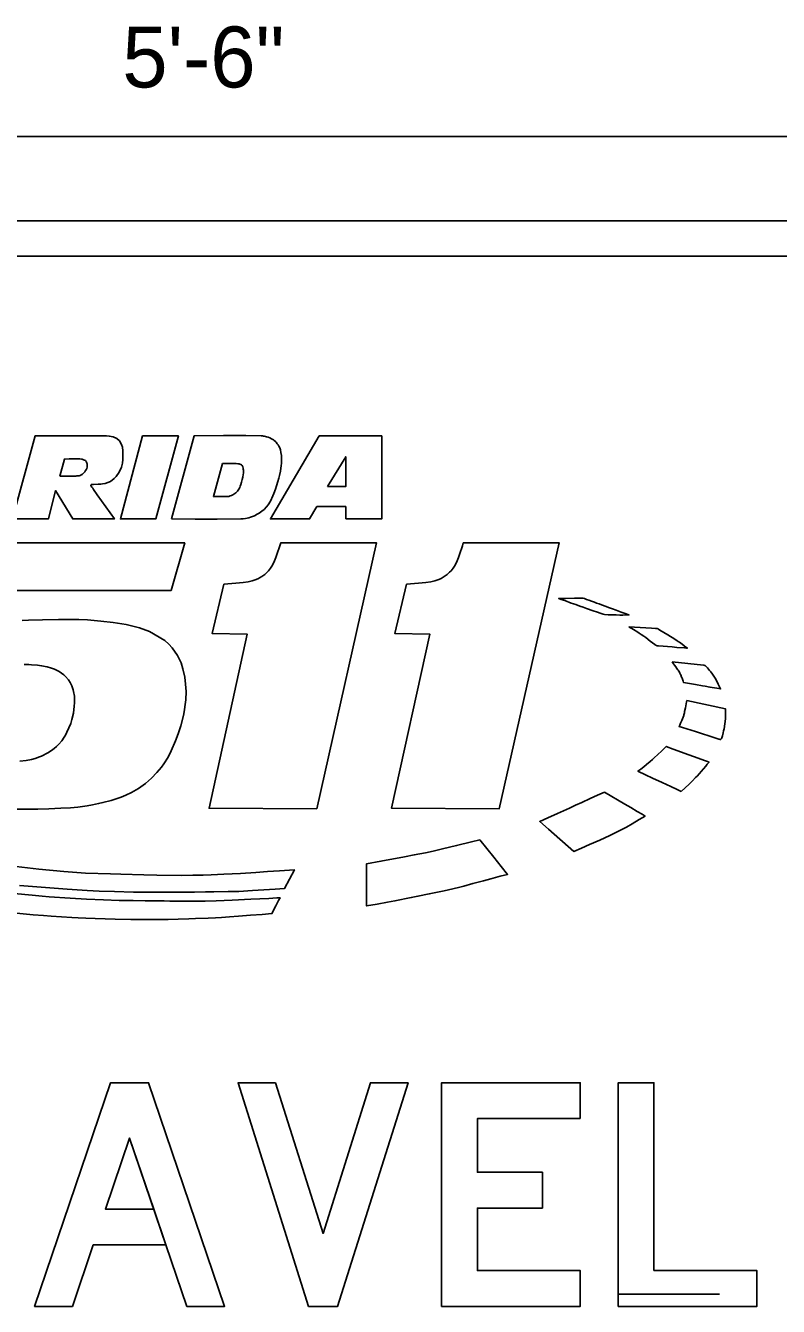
# Model space of a CAD drawing. Extents: x 0 to 770, y 0 to 495.
# Drawn here: x 491.6 to 534.9, y 414.6 to 488.2 of the extents above; entities that cross this region are included whole.
import ezdxf

# ---------------------------------------------------------------- set-up
doc = ezdxf.new("R2010")
doc.units = 0
for name, color, linetype in [('Default', 7, 'Continuous'), ('GSBWFill', 7, 'Continuous'), ('GSColorFill', 7, 'Continuous'), ('GSDims', 7, 'Continuous'), ('GSOutline', 7, 'Continuous'), ('TextStructures', 7, 'Continuous')]:
    doc.layers.add(name, color=color, linetype=linetype)

msp = doc.modelspace()

# ---------------------------------------------------------------- linework, layer by layer
at = {"layer": 'Default'}
for p, q in [((545.381, 477.014), (459.981, 477.014)), ((459.981, 477.014), (545.381, 477.014)), ((545.381, 474.981), (459.981, 474.981)), ((492.158, 464.666), (496.254, 464.666)), ((522.264, 458.513), (518.823, 443.244)), ((512.639, 443.267), (514.826, 453.278)), ((525.612, 415.349), (531.47, 415.349))]:
    msp.add_line(p, q, dxfattribs=at)
for points in [[(496.254, 464.666), (496.42, 464.656), (496.647, 464.609), (496.859, 464.51), (497.004, 464.382), (497.128, 464.17), (497.176, 464.017), (497.206, 463.809), (497.193, 463.297), (497.175, 463.103), (497.118, 462.866), (496.993, 462.583), (496.993, 462.583), (496.818, 462.337), (496.692, 462.208), (496.483, 462.05), (496.483, 462.05), (496.184, 461.923), (496.039, 461.905), (495.929, 461.894), (495.782, 461.882), (495.782, 461.882), (495.506, 461.868), (495.417, 461.866), (495.38, 461.865), (495.38, 461.857), (495.373, 461.838), (495.368, 461.836), (495.361, 461.828), (495.358, 461.809), (495.375, 461.781), (495.423, 461.713), (495.467, 461.65), (495.514, 461.585), (495.728, 461.284), (496.719, 459.891), (494.317, 459.891), (493.336, 461.518), (492.923, 459.891), (490.863, 459.891), (492.158, 464.666)], [(498.333, 464.666), (500.387, 464.666), (499.092, 459.891), (497.063, 459.891)], [(499.992, 459.891), (501.295, 464.666), (502.99, 464.684), (504.259, 464.679), (505.153, 464.666), (505.231, 464.661), (505.268, 464.656), (505.319, 464.649), (505.387, 464.635), (505.454, 464.618), (505.541, 464.591), (505.638, 464.552), (505.737, 464.503), (505.846, 464.437), (505.888, 464.407), (505.958, 464.344), (506.008, 464.293), (506.072, 464.215), (506.115, 464.153), (506.166, 464.065), (506.209, 463.972), (506.249, 463.854), (506.283, 463.707), (506.309, 463.542), (506.319, 463.421), (506.32, 463.175), (506.314, 463.103), (506.299, 462.951), (506.279, 462.804), (506.252, 462.644), (506.198, 462.395), (506.155, 462.23), (506.104, 462.05), (506.027, 461.799), (505.959, 461.593), (505.874, 461.358), (505.818, 461.214), (505.671, 460.908), (505.543, 460.706), (505.446, 460.578), (505.446, 460.578), (505.307, 460.437), (505.307, 460.437), (505.187, 460.335), (505.187, 460.335), (505.023, 460.218), (504.92, 460.156), (504.92, 460.156), (504.754, 460.072), (504.537, 459.989), (504.43, 459.958), (504.246, 459.919), (504.117, 459.901), (503.98, 459.892), (502.622, 459.875), (501.353, 459.874)], [(510.004, 459.891), (512.071, 459.891), (512.071, 464.666), (508.481, 464.666), (505.675, 459.891), (507.927, 459.891), (508.344, 460.602), (510.004, 460.602)], [(493.583, 462.347), (493.84, 463.335), (494.115, 463.346), (494.292, 463.348), (494.455, 463.347), (494.626, 463.341), (494.728, 463.336), (494.821, 463.326), (494.87, 463.316), (494.946, 463.294), (494.99, 463.276), (495.045, 463.243), (495.082, 463.205), (495.102, 463.177), (495.116, 463.151), (495.135, 463.089), (495.142, 463.057), (495.148, 463.015), (495.15, 462.958), (495.146, 462.901), (495.14, 462.861), (495.123, 462.798), (495.102, 462.747), (495.068, 462.684), (495.057, 462.667), (495.007, 462.595), (494.983, 462.566), (494.947, 462.527), (494.895, 462.479), (494.891, 462.476), (494.853, 462.447), (494.81, 462.42), (494.782, 462.406), (494.742, 462.391), (494.742, 462.391), (494.688, 462.377), (494.636, 462.37), (494.578, 462.363), (494.541, 462.359), (494.517, 462.357), (494.473, 462.355), (494.434, 462.354), (494.161, 462.352), (493.815, 462.349)], [(502.924, 463.082), (503.062, 463.083), (503.239, 463.085), (503.341, 463.086), (503.415, 463.086), (503.501, 463.084), (503.609, 463.079), (503.662, 463.075), (503.715, 463.07), (503.802, 463.061), (503.86, 463.053), (503.895, 463.048), (503.926, 463.039), (503.969, 463.02), (504.01, 462.991), (504.045, 462.954), (504.083, 462.887), (504.086, 462.879), (504.107, 462.811), (504.118, 462.758), (504.126, 462.695), (504.129, 462.634), (504.127, 462.572), (504.123, 462.528), (504.114, 462.45), (504.09, 462.294), (504.061, 462.153), (504.021, 462.005), (503.98, 461.877), (503.941, 461.774), (503.911, 461.699), (503.855, 461.593), (503.784, 461.493), (503.683, 461.389), (503.629, 461.345), (503.516, 461.273), (503.439, 461.236), (503.37, 461.21), (503.292, 461.189), (503.213, 461.178), (503.135, 461.176), (502.928, 461.176), (502.725, 461.176), (502.562, 461.176), (502.397, 461.176)], [(508.961, 461.75), (510.004, 463.464), (510.004, 461.75)], [(502.994, 456.148), (503.696, 456.198), (504.115, 456.246), (504.395, 456.286), (504.632, 456.335), (504.859, 456.413), (505, 456.477), (505.043, 456.5), (505.176, 456.579), (505.289, 456.659), (505.348, 456.706), (505.481, 456.825), (505.561, 456.909), (505.68, 457.057), (505.766, 457.185), (505.82, 457.279), (505.918, 457.488), (505.987, 457.674), (506.087, 457.954), (506.181, 458.238), (506.216, 458.35), (506.266, 458.513), (511.776, 458.513), (508.335, 443.244), (502.151, 443.267), (504.337, 453.278), (502.337, 453.301)], [(513.483, 456.148), (514.185, 456.198), (514.604, 456.246), (514.883, 456.286), (515.121, 456.335), (515.348, 456.412), (515.488, 456.477), (515.532, 456.5), (515.664, 456.579), (515.777, 456.659), (515.837, 456.705), (515.969, 456.825), (516.049, 456.909), (516.169, 457.057), (516.255, 457.185), (516.309, 457.279), (516.406, 457.488), (516.475, 457.674), (516.575, 457.954), (516.669, 458.238), (516.705, 458.35), (516.754, 458.513), (522.264, 458.513), (518.823, 443.244), (512.639, 443.267), (514.826, 453.278), (512.826, 453.301)], [(526.253, 454.377), (526.272, 454.378), (526.059, 454.456), (525.827, 454.541), (525.538, 454.647), (525.318, 454.728), (525.095, 454.809), (524.954, 454.861), (524.693, 454.957), (524.565, 455.004), (524.414, 455.059), (524.285, 455.106), (524.123, 455.165), (523.958, 455.226), (523.835, 455.271), (523.722, 455.312), (523.634, 455.344), (523.428, 455.341), (523.139, 455.336), (522.634, 455.327), (522.242, 455.32), (522.375, 455.271), (522.581, 455.196), (522.957, 455.06), (523.213, 454.967), (523.456, 454.878), (523.631, 454.813), (523.838, 454.738), (524.207, 454.611), (524.461, 454.529), (524.618, 454.479), (524.791, 454.427), (524.873, 454.403), (525.077, 454.39), (525.538, 454.373), (525.748, 454.37), (525.917, 454.371), (526.031, 454.372), (526.139, 454.374), (526.221, 454.376)], [(526.257, 453.695), (526.92, 453.657), (527.571, 453.618), (527.799, 453.605), (527.84, 453.603), (527.854, 453.602), (527.87, 453.599), (527.88, 453.597), (527.891, 453.595), (527.905, 453.591), (527.915, 453.587), (527.929, 453.581), (527.945, 453.573), (527.961, 453.563), (527.974, 453.555), (528.05, 453.508), (528.273, 453.37), (528.495, 453.232), (528.9, 452.981), (529.04, 452.894), (529.106, 452.853), (529.223, 452.766), (529.435, 452.609), (529.541, 452.53), (529.625, 452.468), (529.604, 452.469), (529.567, 452.472), (529.507, 452.477), (529.461, 452.48), (529.028, 452.513), (528.748, 452.535), (527.958, 452.596), (527.917, 452.6), (527.877, 452.606), (527.861, 452.611), (527.826, 452.627), (527.808, 452.639), (527.775, 452.663), (527.757, 452.677), (527.496, 452.876), (527.235, 453.076), (527.12, 453.163), (526.972, 453.26), (526.856, 453.335), (526.776, 453.385), (526.693, 453.437), (526.627, 453.477), (526.524, 453.539), (526.433, 453.593), (526.323, 453.658), (526.296, 453.673), (526.27, 453.688)], [(528.756, 451.674), (530.561, 451.484), (530.567, 451.484), (530.573, 451.483), (530.578, 451.483), (530.584, 451.482), (530.587, 451.482), (530.594, 451.481), (530.602, 451.479), (530.61, 451.477), (530.618, 451.475), (530.623, 451.473), (530.631, 451.471), (530.636, 451.469), (530.642, 451.466), (530.649, 451.462), (530.655, 451.458), (530.666, 451.45), (530.672, 451.445), (530.679, 451.439), (530.711, 451.405), (530.773, 451.337), (530.845, 451.254), (530.904, 451.184), (530.97, 451.1), (531.062, 450.976), (531.11, 450.906), (531.252, 450.685), (531.395, 450.404), (531.537, 450.126), (531.447, 450.141), (531.186, 450.186), (530.919, 450.232), (530.655, 450.277), (530.486, 450.306), (530.101, 450.372), (529.756, 450.432), (529.517, 450.473), (529.404, 450.492), (529.376, 450.569), (529.317, 450.735), (529.303, 450.775), (529.277, 450.847), (529.26, 450.892), (529.238, 450.944), (529.198, 451.029), (529.17, 451.083), (529.134, 451.145), (529.097, 451.203), (529.067, 451.247), (529.027, 451.301), (528.964, 451.388), (528.891, 451.488), (528.829, 451.573)], [(529.586, 449.451), (531.815, 448.986), (531.815, 448.701), (531.815, 448.416), (531.8, 448.254), (531.784, 448.124), (531.738, 447.833), (531.709, 447.717), (531.678, 447.594), (531.639, 447.432), (531.599, 447.306), (531.599, 447.306), (531.581, 447.274), (531.572, 447.259), (531.565, 447.25), (531.554, 447.239), (531.544, 447.23), (531.541, 447.227), (531.538, 447.226), (531.535, 447.224), (531.531, 447.223), (531.526, 447.222), (531.521, 447.222), (531.514, 447.223), (531.508, 447.224), (531.493, 447.227), (531.474, 447.232), (531.452, 447.239), (531.438, 447.244), (531.253, 447.302), (530.089, 447.669), (529.342, 447.905), (529.161, 447.962), (529.152, 447.965), (529.166, 447.997), (529.189, 448.05), (529.233, 448.148), (529.304, 448.309), (529.349, 448.412), (529.386, 448.501), (529.42, 448.602), (529.43, 448.638), (529.442, 448.685), (529.456, 448.745), (529.47, 448.824), (529.51, 449.041), (529.574, 449.387)], [(529.275, 444.234), (529.722, 444.649), (529.923, 444.847), (530.098, 445.026), (530.185, 445.118), (530.314, 445.259), (530.42, 445.378), (530.546, 445.524), (530.677, 445.679), (530.77, 445.792), (530.869, 445.915), (530.787, 445.945), (530.604, 446.012), (530.242, 446.146), (529.709, 446.343), (528.816, 446.672), (528.408, 446.823), (528.297, 446.709), (528.131, 446.542), (527.929, 446.348), (527.727, 446.161), (527.623, 446.067), (527.496, 445.959), (527.275, 445.776), (527.126, 445.657), (526.944, 445.516), (526.787, 445.399), (527.229, 445.193), (527.629, 445.005), (528.17, 444.752), (528.67, 444.518), (529.031, 444.348)], [(524.874, 444.198), (526.035, 443.509), (526.384, 443.302), (526.745, 443.087), (527.026, 442.92), (527.196, 442.819), (526.856, 442.615), (526.456, 442.375), (526.125, 442.183), (525.64, 441.927), (525.18, 441.701), (524.595, 441.433), (524.011, 441.181), (523.548, 440.981), (523.1, 440.787), (521.649, 442.067), (521.147, 442.509), (521.604, 442.716), (522.175, 442.975), (522.854, 443.282), (523.195, 443.437), (523.56, 443.602), (524.038, 443.819), (524.465, 444.013)], [(517.705, 441.457), (518.501, 440.463), (518.932, 439.926), (519.298, 439.469), (518.881, 439.358), (518.345, 439.214), (517.923, 439.101), (517.311, 438.937), (517.311, 438.937), (516.791, 438.797), (516.555, 438.734), (516.147, 438.641), (515.655, 438.531), (514.798, 438.346), (514.151, 438.211), (513.761, 438.132), (512.826, 437.948), (512.392, 437.865), (511.812, 437.763), (511.198, 437.655), (511.198, 438.221), (511.198, 438.869), (511.198, 439.245), (511.198, 440.083), (511.198, 440.083), (512.021, 440.226), (512.021, 440.226), (513.383, 440.478), (513.937, 440.586), (514.578, 440.716), (515.02, 440.808), (515.556, 440.929), (516.372, 441.121), (517.222, 441.332)]]:
    msp.add_lwpolyline(points, close=True, dxfattribs=at)
for points in [[(485.362, 458.513), (500.755, 458.513), (499.97, 455.78), (490.739, 455.78)], [(491.423, 454.059), (491.784, 454.071), (492.578, 454.091), (493.502, 454.105), (494.289, 454.109), (494.675, 454.107), (495.166, 454.094), (495.927, 454.027), (496.636, 453.943), (497.383, 453.829), (498.159, 453.634), (498.733, 453.429), (498.733, 453.429), (499.61, 452.907), (499.839, 452.697), (500.037, 452.477), (500.338, 452.042), (500.544, 451.614), (500.653, 451.288), (500.757, 450.793), (500.807, 450.397), (500.828, 449.973), (500.813, 449.492), (500.767, 449.092), (500.74, 448.931), (500.685, 448.597), (500.527, 447.999), (500.384, 447.553), (500.228, 447.143), (499.983, 446.573), (499.794, 446.208), (499.556, 445.828), (499.416, 445.635), (499.158, 445.32), (498.837, 444.989), (498.5, 444.697), (498.099, 444.409), (497.699, 444.173), (497.38, 444.018), (497.101, 443.903), (496.533, 443.72), (496.052, 443.595), (495.803, 443.538), (495.46, 443.469), (495.14, 443.413), (494.606, 443.34), (494.19, 443.299), (493.64, 443.267), (492.957, 443.232), (492.312, 443.212), (492.312, 443.212), (490.561, 443.213)], [(491.279, 445.97), (491.645, 446.012), (491.951, 446.074), (492.167, 446.133), (492.417, 446.218), (492.536, 446.265), (492.897, 446.449), (493.093, 446.578), (493.262, 446.709), (493.393, 446.825), (493.521, 446.953), (493.689, 447.15), (493.827, 447.343), (493.903, 447.471), (493.991, 447.636), (493.991, 447.636), (494.203, 448.137), (494.272, 448.359), (494.356, 448.733), (494.412, 449.136), (494.425, 449.325), (494.424, 449.532), (494.413, 449.7), (494.372, 449.973), (494.35, 450.071), (494.27, 450.31), (494.182, 450.488), (494.083, 450.642), (493.907, 450.847), (493.801, 450.941), (493.532, 451.129), (493.274, 451.257), (493.099, 451.32), (492.849, 451.39), (492.53, 451.456), (492.29, 451.488), (491.946, 451.51), (491.795, 451.519), (491.537, 451.52)], [(491.08, 439.922), (492.376, 439.77), (493.804, 439.635), (495.052, 439.547), (496.482, 439.495), (497.091, 439.477), (498.399, 439.444), (499.157, 439.429), (500.561, 439.41), (501.217, 439.419), (501.822, 439.433), (502.263, 439.446), (503.009, 439.475), (503.952, 439.523), (504.836, 439.583), (505.512, 439.629), (506.188, 439.675), (507.058, 439.734), (506.492, 438.663), (505.951, 438.628), (504.649, 438.543), (503.869, 438.491), (503.253, 438.479), (502.432, 438.465), (501.946, 438.459), (501.309, 438.452), (500.839, 438.448), (499.671, 438.442), (498.425, 438.442), (497.802, 438.445), (496.721, 438.477), (495.838, 438.513), (495.142, 438.547), (493.995, 438.615), (493.258, 438.667), (492, 438.77), (491.27, 438.837)], [(490.954, 438.372), (491.997, 438.27), (492.563, 438.22), (492.958, 438.188), (494.172, 438.1), (495.113, 438.045), (496.083, 437.999), (496.986, 437.975), (497.798, 437.961), (498.481, 437.952), (499.582, 437.941), (499.899, 437.939), (500.465, 437.937), (501.308, 437.936), (501.919, 437.938), (502.567, 437.946), (503.469, 437.985), (504.559, 438.036), (505.593, 438.089), (506.037, 438.114), (506.23, 438.125), (506.145, 437.961), (505.994, 437.671), (505.757, 437.217), (505.211, 437.172), (504.524, 437.118), (503.848, 437.067), (503.334, 437.031), (502.864, 436.999), (502.52, 436.976), (502.102, 436.956), (501.377, 436.926), (500.98, 436.912), (500.386, 436.896), (499.801, 436.884), (499.116, 436.876), (498.343, 436.874), (497.659, 436.879), (496.766, 436.895), (496.181, 436.911), (495.615, 436.931), (495.082, 436.953), (494.639, 436.974), (494.269, 436.994), (493.682, 437.029), (493.076, 437.07), (492.642, 437.103), (492.049, 437.151), (491.082, 437.239)]]:
    msp.add_lwpolyline(points, dxfattribs=at)
at = {"layer": 'GSBWFill'}
for points in [[(492.128, 414.647), (496.495, 427.492), (498.679, 427.492), (503.046, 414.647), (500.876, 414.647), (497.587, 424.319), (496.198, 420.233), (498.976, 420.233), (499.674, 418.178), (495.5, 418.178), (494.299, 414.647)], [(505.972, 427.492), (508.698, 418.837), (511.424, 427.492), (513.579, 427.492), (509.533, 414.647), (507.863, 414.647), (503.817, 427.492)], [(523.469, 425.437), (517.561, 425.437), (517.561, 422.354), (521.296, 422.354), (521.296, 420.299), (517.561, 420.299), (517.561, 416.702), (523.469, 416.702), (523.469, 414.647), (515.506, 414.647), (515.506, 427.492), (523.469, 427.492)], [(527.708, 416.702), (533.617, 416.702), (533.617, 414.647), (525.653, 414.647), (525.653, 427.492), (527.708, 427.492)]]:
    msp.add_lwpolyline(points, close=True, dxfattribs=at)
at = {"layer": 'GSColorFill'}
for points in [[(492.128, 414.647), (496.495, 427.492), (498.679, 427.492), (503.046, 414.647), (500.876, 414.647), (497.587, 424.319), (496.198, 420.233), (498.976, 420.233), (499.674, 418.178), (495.5, 418.178), (494.299, 414.647)], [(505.972, 427.492), (508.698, 418.837), (511.424, 427.492), (513.579, 427.492), (509.533, 414.647), (507.863, 414.647), (503.817, 427.492)], [(523.469, 425.437), (517.561, 425.437), (517.561, 422.354), (521.296, 422.354), (521.296, 420.299), (517.561, 420.299), (517.561, 416.702), (523.469, 416.702), (523.469, 414.647), (515.506, 414.647), (515.506, 427.492), (523.469, 427.492)], [(527.708, 416.702), (533.617, 416.702), (533.617, 414.647), (525.653, 414.647), (525.653, 427.492), (527.708, 427.492)]]:
    msp.add_lwpolyline(points, close=True, dxfattribs=at)
at = {"layer": 'GSDims'}
msp.add_line((454.175, 481.858), (551.481, 481.858), dxfattribs=at)
at = {"layer": 'GSOutline'}
for points in [[(495.5, 418.178), (494.299, 414.647), (492.128, 414.647), (496.495, 427.492), (498.679, 427.492), (503.046, 414.647), (500.876, 414.647), (499.675, 418.178)], [(505.972, 427.492), (508.698, 418.837), (511.424, 427.492), (513.579, 427.492), (509.533, 414.647), (507.863, 414.647), (503.817, 427.492)], [(523.469, 425.437), (517.561, 425.437), (517.561, 422.354), (521.296, 422.354), (521.296, 420.299), (517.561, 420.299), (517.561, 416.702), (523.469, 416.702), (523.469, 414.647), (515.506, 414.647), (515.506, 427.492), (523.469, 427.492)], [(527.708, 416.702), (533.617, 416.702), (533.617, 414.647), (525.653, 414.647), (525.653, 427.492), (527.708, 427.492)], [(496.198, 420.233), (498.976, 420.233), (497.587, 424.319)]]:
    msp.add_lwpolyline(points, close=True, dxfattribs=at)

# ---------------------------------------------------------------- texts
at = {"layer": 'TextStructures'}
msp.add_text('5\'-6"', height=3.5, dxfattribs=at).set_placement((497.167, 484.684))

doc.saveas('drawing.dxf')
